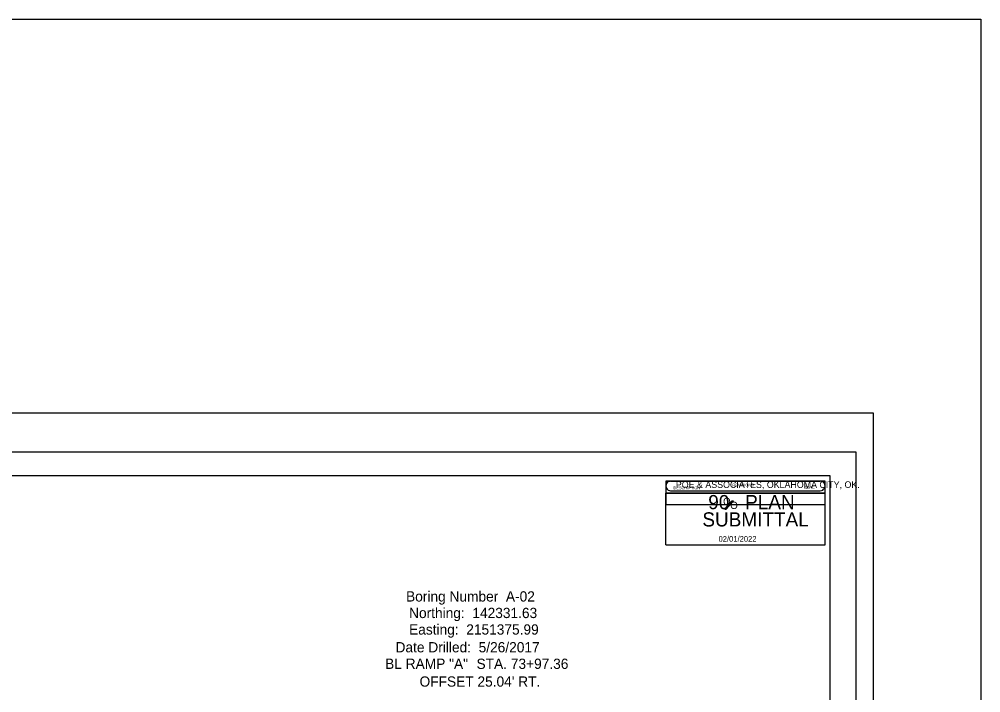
# Model space of a CAD drawing. Extents: x 2150161.5 to 2150203.1, y 143779.5 to 143868.5.
# Drawn here: x 2150182.73 to 2150203.07, y 143854.22 to 143868.48 of the extents above; entities that cross this region are included whole.
import ezdxf

# ---------------------------------------------------------------- set-up
doc = ezdxf.new("R2010")
doc.units = 0
for name, color, linetype in [('Default', 7, 'Continuous'), ('S', 7, 'Continuous'), ('SHT_Plot_Shape_Full', 7, 'Continuous'), ('SHT_Plot_Shape_Half', 7, 'Continuous'), ('SHT_Sheet_Border', 7, 'Continuous'), ('SHT_Stamp_90_Submit', 7, 'Continuous'), ('SHT_Stamp_Rev_Block', 7, 'Continuous'), ('SHT_Stamp_Rev_Prop_RW', 7, 'Continuous')]:
    doc.layers.add(name, color=color, linetype=linetype)

msp = doc.modelspace()

# ---------------------------------------------------------------- linework, layer by layer
at = {"layer": 'S'}
msp.add_lwpolyline([(2150161.53, 143868.477), (2150203.071, 143868.477), (2150203.071, 143779.536), (2150161.53, 143779.536)], close=True, dxfattribs=at)
at = {"layer": 'SHT_Plot_Shape_Full'}
msp.add_lwpolyline([(2150164.792, 143860.145), (2150200.792, 143860.145), (2150200.792, 143836.145), (2150164.792, 143836.145)], close=True, dxfattribs=at)
at = {"layer": 'SHT_Plot_Shape_Half'}
msp.add_lwpolyline([(2150166.429, 143859.32), (2150200.429, 143859.32), (2150200.429, 143837.32), (2150166.429, 143837.32)], close=True, dxfattribs=at)
at = {"layer": 'SHT_Sheet_Border'}
msp.add_lwpolyline([(2150199.879, 143837.82), (2150168.379, 143837.82), (2150168.379, 143858.82), (2150199.879, 143858.82)], close=True, dxfattribs=at)
at = {"layer": 'SHT_Stamp_90_Submit'}
for p, q in [((2150196.51, 143858.696), (2150199.676, 143858.696)), ((2150196.41, 143858.446), (2150199.776, 143858.446)), ((2150196.41, 143857.347), (2150196.41, 143858.446)), ((2150196.51, 143858.496), (2150199.676, 143858.496)), ((2150199.776, 143857.347), (2150199.776, 143858.446)), ((2150197.653, 143858.108), (2150197.809, 143858.281)), ((2150197.653, 143858.108), (2150197.684, 143858.108)), ((2150197.671, 143858.108), (2150197.827, 143858.281)), ((2150197.676, 143858.108), (2150197.832, 143858.281)), ((2150197.684, 143858.108), (2150197.839, 143858.281)), ((2150197.809, 143858.281), (2150197.839, 143858.281)), ((2150196.41, 143857.347), (2150199.776, 143857.347))]:
    msp.add_line(p, q, dxfattribs=at)
for centre, start, end in [((2150196.51, 143858.596), 89.9952, 270), ((2150199.676, 143858.596), 270, 90.0048)]:
    msp.add_arc(centre, 0.1, start, end, dxfattribs=at)
at = {"layer": 'SHT_Stamp_Rev_Block'}
for p, q in [((2150196.41, 143858.696), (2150196.41, 143858.196)), ((2150199.776, 143858.696), (2150196.41, 143858.696)), ((2150199.776, 143858.196), (2150199.776, 143858.696)), ((2150199.776, 143858.446), (2150196.41, 143858.446)), ((2150199.776, 143858.196), (2150196.41, 143858.196))]:
    msp.add_line(p, q, dxfattribs=at)

# ---------------------------------------------------------------- texts
at = {"layer": 'Default'}
for s, p in [('Boring Number  A-02', (2150190.912, 143856.149)), ('Northing:  142331.63', (2150190.976, 143855.799)), ('Easting:  2151375.99', (2150190.976, 143855.449)), ('Date Drilled:  5/26/2017', (2150190.69, 143855.073)), ('BL RAMP "A" ', (2150190.469, 143854.723)), ('STA. 73+97.36', (2150192.403, 143854.723)), ("OFFSET 25.04' RT.", (2150191.198, 143854.347))]:
    msp.add_text(s, height=0.217, dxfattribs=at).set_placement(p)
at = {"layer": 'SHT_Stamp_90_Submit'}
for s, height, p in [('POE & ASSOCIATES, OKLAHOMA CITY, OK.', 0.14, (2150196.62, 143858.554)), ('90   PLAN', 0.3, (2150197.305, 143858.104)), ('O', 0.153, (2150197.619, 143858.193)), ('O', 0.153, (2150197.771, 143858.109)), ('SUBMITTAL', 0.3, (2150197.181, 143857.738))]:
    msp.add_text(s, height=height, dxfattribs=at).set_placement(p)
at = {"layer": 'SHT_Stamp_Rev_Block'}
for s, height, p in [('DESCRIPTION', 0.05999, (2150196.57, 143858.525)), ('REVISIONS', 0.06, (2150197.818, 143858.584)), ('DATE', 0.06, (2150199.34, 143858.529))]:
    msp.add_text(s, height=height, dxfattribs=at).set_placement(p)
at = {"layer": 'SHT_Stamp_Rev_Prop_RW'}
msp.add_text('02/01/2022', height=0.12, dxfattribs=at).set_placement((2150197.523, 143857.415))

doc.saveas('drawing.dxf')
